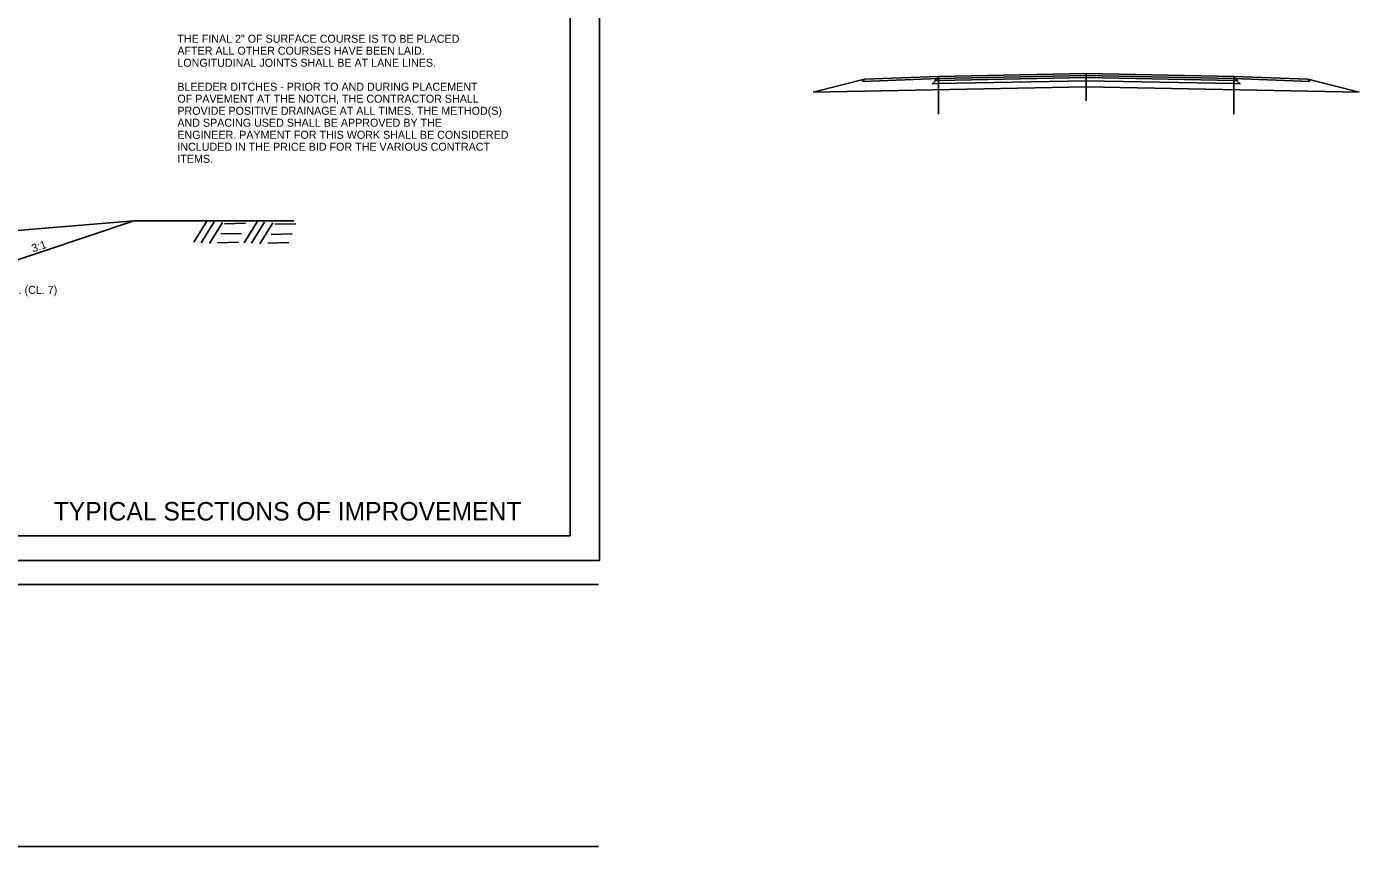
# Model space of a CAD drawing. Extents: x 1373719 to 1374161, y 379835 to 380167.
# Drawn here: x 1373999.9 to 1374108.2, y 380009.8 to 380076.3 of the extents above; entities that cross this region are included whole.
import ezdxf

# ---------------------------------------------------------------- set-up
doc = ezdxf.new("R2010")
doc.units = 0
for name, color, linetype in [('Agg Base Course Text', 7, 'Continuous'), ('DATE', 7, 'Continuous'), ('GREEN_TXT', 7, 'Continuous'), ('Ground Hatch', 7, 'Continuous'), ('R_NoPlot', 7, 'Continuous'), ('T_Drafting', 7, 'Continuous')]:
    doc.layers.add(name, color=color, linetype=linetype)

msp = doc.modelspace()

# ---------------------------------------------------------------- linework, layer by layer
msp.add_line((1373995.71, 380056.22), (1374008.61, 380060.53))
at = {"layer": 'DATE'}
for p, q in [((1374044.06, 380034.96), (1374044.06, 380137.69)), ((1374044.06, 380034.96), (1373885.97, 380034.96)), ((1373870.36, 380031.02), (1374046.36, 380031.02)), ((1374046.36, 380009.75), (1373870.36, 380009.75))]:
    msp.add_line(p, q, dxfattribs=at)
at = {"layer": 'Ground Hatch'}
for p, q in [((1374013.47, 380058.8), (1374014.53, 380060.51)), ((1374014.07, 380058.75), (1374015.13, 380060.46)), ((1374017.56, 380058.76), (1374018.63, 380060.47)), ((1374014.74, 380058.71), (1374015.8, 380060.41)), ((1374015.67, 380059.48), (1374017.36, 380059.52)), ((1374015.97, 380060.3), (1374017.67, 380060.34)), ((1374018.16, 380058.72), (1374019.23, 380060.42)), ((1374018.83, 380058.67), (1374019.89, 380060.38)), ((1374019.76, 380059.44), (1374021.46, 380059.48)), ((1374020.07, 380060.26), (1374021.76, 380060.3)), ((1374015.4, 380058.76), (1374017.1, 380058.8)), ((1374019.49, 380058.72), (1374021.19, 380058.77))]:
    msp.add_line(p, q, dxfattribs=at)
at = {"layer": 'R_NoPlot'}
msp.add_lwpolyline([(1373879.77, 380139.64), (1374046.44, 380139.64), (1374046.44, 380032.97), (1373879.77, 380032.97)], close=True, dxfattribs=at)
at = {"layer": 'T_Drafting'}
for p, q in [((1374085.97, 380072.51), (1374085.97, 380070.29)), ((1374085.97, 380072.51), (1374085.97, 380070.29)), ((1374067.97, 380072.03), (1374063.79, 380070.98)), ((1374085.97, 380071.42), (1374063.79, 380070.98)), ((1374073.97, 380072.27), (1374073.97, 380069.21)), ((1374085.97, 380071.42), (1374108.16, 380070.98)), ((1374097.97, 380072.27), (1374097.97, 380069.21)), ((1374103.97, 380072.03), (1374108.16, 380070.98))]:
    msp.add_line(p, q, dxfattribs=at)
for points in [[(1374085.97, 380072.51), (1374073.97, 380072.27), (1374067.97, 380072.03), (1374067.81, 380071.86), (1374073.97, 380072.1), (1374085.97, 380072.34)], [(1374085.97, 380072.51), (1374097.97, 380072.27), (1374103.97, 380072.03), (1374104.14, 380071.86), (1374097.97, 380072.1), (1374085.97, 380072.34)], [(1374073.97, 380071.93), (1374073.72, 380071.92), (1374073.47, 380071.67), (1374073.97, 380071.68), (1374085.97, 380071.92)], [(1374073.97, 380072.1), (1374073.85, 380072.1), (1374073.68, 380071.93), (1374073.97, 380071.93), (1374085.97, 380072.17)], [(1374097.97, 380072.1), (1374098.1, 380072.1), (1374098.27, 380071.93), (1374097.97, 380071.93), (1374085.97, 380072.17)], [(1374097.97, 380071.93), (1374098.22, 380071.92), (1374098.47, 380071.67), (1374097.97, 380071.68), (1374085.97, 380071.92)], [(1373907.68, 380053.14), (1373924.23, 380053.06), (1373943.14, 380055.23), (1373951.91, 380058.53), (1373953.6, 380058.69), (1373964.74, 380058.7), (1373975.62, 380058.45), (1373977.35, 380058.29), (1373984.39, 380055.64), (1373996.46, 380059.55), (1374008.61, 380060.53), (1374021.6, 380060.53)]]:
    msp.add_lwpolyline(points, dxfattribs=at)

# ---------------------------------------------------------------- texts
at = {"layer": 'Agg Base Course Text'}
msp.add_text('AGGREGATE BASE CRSE. (CL. 7)', height=0.65, dxfattribs=at).set_placement((1373988.52, 380054.61))
at = {"layer": 'DATE'}
msp.add_text('TYPICAL SECTIONS OF IMPROVEMENT', height=1.5, dxfattribs=at).set_placement((1374002.09, 380036.21))
at = {"layer": 'GREEN_TXT'}
for s, p in [('THE FINAL 2" OF SURFACE COURSE IS TO BE PLACED ', (1374012.14, 380075)), ('AFTER ALL OTHER COURSES HAVE BEEN LAID. ', (1374012.14, 380074.03)), ('LONGITUDINAL JOINTS SHALL BE AT LANE LINES.', (1374012.14, 380073.05)), ('BLEEDER DITCHES - PRIOR TO AND DURING PLACEMENT', (1374012.14, 380071.1)), ('OF PAVEMENT AT THE NOTCH, THE CONTRACTOR SHALL', (1374012.14, 380070.13)), ('PROVIDE POSITIVE DRAINAGE AT ALL TIMES. THE METHOD(S)', (1374012.14, 380069.15)), ('AND SPACING USED SHALL BE APPROVED BY THE', (1374012.14, 380068.18)), ('ENGINEER. PAYMENT FOR THIS WORK SHALL BE CONSIDERED', (1374012.14, 380067.2)), ('INCLUDED IN THE PRICE BID FOR THE VARIOUS CONTRACT', (1374012.14, 380066.23)), ('ITEMS.', (1374012.14, 380065.25))]:
    msp.add_text(s, height=0.65, dxfattribs=at).set_placement(p)
msp.add_text('3:1', height=0.65, rotation=18.4782, dxfattribs=at).set_placement((1374000.42, 380057.97))

doc.saveas('drawing.dxf')
